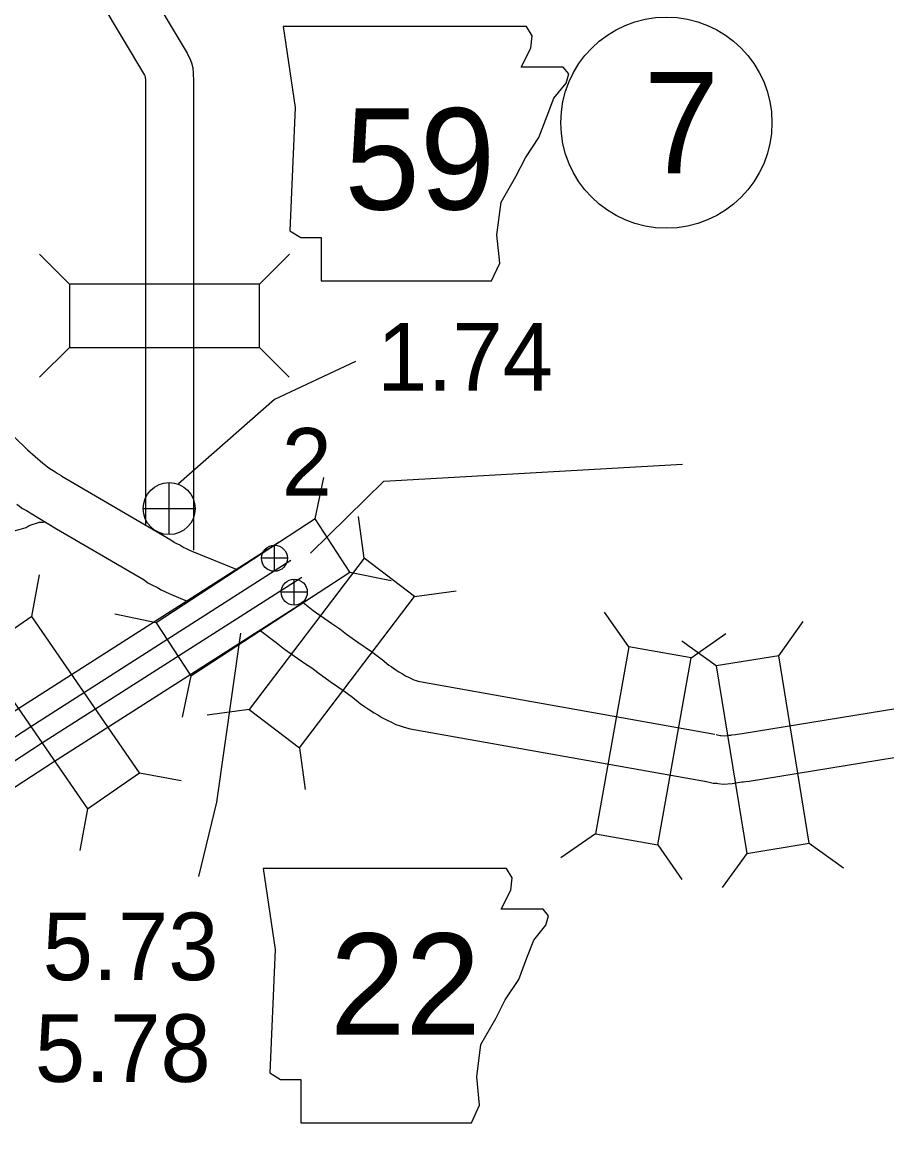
# Model space of a CAD drawing. Extents: x -939622 to -934245, y 1383184 to 1385301.
# Drawn here: x -936388.54 to -936372.33, y 1384539.92 to 1384560.75 of the extents above; entities that cross this region are included whole.
import ezdxf

# ---------------------------------------------------------------- set-up
doc = ezdxf.new("R2010")
doc.units = 0
for name, color, linetype in [('Level 10', 7, 'Continuous'), ('Level 20', 7, 'Continuous'), ('Level 21', 7, 'Continuous'), ('Level 25', 7, 'Continuous'), ('Level 26', 7, 'Continuous'), ('Level 27', 7, 'Continuous')]:
    doc.layers.add(name, color=color, linetype=linetype)

msp = doc.modelspace()

# ---------------------------------------------------------------- linework, layer by layer
at = {"layer": 'Level 10'}
for points in [[(-936387.073, 1384562.893), (-936385.448, 1384560.175), (-936385.424, 1384560.119), (-936385.4, 1384560.072), (-936385.37, 1384559.993), (-936385.345, 1384559.897), (-936385.337, 1384559.8), (-936385.337, 1384559.765), (-936385.333, 1384559.682), (-936385.334, 1384550.854)], [(-936387.907, 1384562.535), (-936386.249, 1384559.761), (-936386.237, 1384559.733), (-936386.236, 1384559.731), (-936386.233, 1384559.661), (-936386.234, 1384551.336)], [(-936389.27, 1384553.543), (-936389.22, 1384553.489), (-936389.206, 1384553.47), (-936388.444, 1384552.735), (-936388.158, 1384552.482), (-936388.107, 1384552.445), (-936388.066, 1384552.408), (-936387.996, 1384552.365), (-936387.933, 1384552.327), (-936387.901, 1384552.304), (-936387.816, 1384552.254), (-936387.803, 1384552.24), (-936385.757, 1384551.045), (-936385.696, 1384550.999), (-936385.686, 1384550.994), (-936385.661, 1384550.982), (-936385.587, 1384550.949), (-936385.513, 1384550.905), (-936385.51, 1384550.903), (-936385.481, 1384550.891), (-936385.443, 1384550.87), (-936385.405, 1384550.853), (-936385.365, 1384550.834), (-936384.533, 1384550.494)], [(-936388.642, 1384551.715), (-936388.537, 1384551.631), (-936388.476, 1384551.604), (-936388.463, 1384551.596), (-936388.429, 1384551.576), (-936388.394, 1384551.551), (-936387.898, 1384551.254), (-936386.257, 1384550.295), (-936386.185, 1384550.241), (-936386.086, 1384550.187), (-936386.033, 1384550.163), (-936386.004, 1384550.15), (-936385.988, 1384550.14), (-936385.936, 1384550.107), (-936385.87, 1384550.078), (-936385.841, 1384550.063), (-936385.789, 1384550.039), (-936385.733, 1384550.012), (-936385.461, 1384549.901)], [(-936389.709, 1384551.062), (-936389.691, 1384551.062), (-936389.682, 1384551.062), (-936389.665, 1384551.061), (-936389.547, 1384551.054), (-936389.523, 1384551.056), (-936389.449, 1384551.046), (-936389.302, 1384551.066), (-936389.211, 1384551.095), (-936389.211, 1384551.095), (-936389.167, 1384551.102), (-936388.694, 1384551.216), (-936388.599, 1384551.238), (-936388.47, 1384551.278), (-936388.411, 1384551.315), (-936388.221, 1384551.376), (-936388.219, 1384551.377), (-936388.209, 1384551.378), (-936388.153, 1384551.378), (-936388.109, 1384551.387)], [(-936412.105, 1384514.693), (-936411.981, 1384515.99), (-936411.897, 1384516.546), (-936411.613, 1384517.695), (-936411.366, 1384518.854), (-936411.114, 1384519.957), (-936410.855, 1384520.897), (-936410.434, 1384521.998), (-936409.873, 1384523.209), (-936409.418, 1384524.021), (-936408.853, 1384524.894), (-936407.084, 1384527.227), (-936404.629, 1384530.336), (-936402.743, 1384532.684), (-936399.705, 1384536.545), (-936395.754, 1384541.531), (-936393.808, 1384543.949), (-936392.835, 1384544.906), (-936391.967, 1384545.627), (-936390.884, 1384546.408), (-936388.606, 1384547.89), (-936383.726, 1384551.009)], [(-936411.715, 1384514.439), (-936411.571, 1384515.94), (-936411.492, 1384516.465), (-936411.211, 1384517.603), (-936410.963, 1384518.765), (-936410.714, 1384519.856), (-936410.462, 1384520.768), (-936410.054, 1384521.837), (-936409.505, 1384523.021), (-936409.065, 1384523.808), (-936408.515, 1384524.656), (-936406.758, 1384526.975), (-936404.306, 1384530.079), (-936402.42, 1384532.427), (-936399.382, 1384536.289), (-936395.432, 1384541.274), (-936393.502, 1384543.672), (-936392.558, 1384544.6), (-936391.714, 1384545.301), (-936390.651, 1384546.067), (-936388.383, 1384547.544), (-936383.504, 1384550.662)], [(-936411.365, 1384514.165), (-936411.199, 1384515.894), (-936411.123, 1384516.392), (-936410.846, 1384517.519), (-936410.597, 1384518.684), (-936410.35, 1384519.764), (-936410.106, 1384520.651), (-936409.708, 1384521.691), (-936409.171, 1384522.85), (-936408.743, 1384523.614), (-936408.208, 1384524.441), (-936406.461, 1384526.745), (-936404.013, 1384529.845), (-936402.127, 1384532.194), (-936399.087, 1384536.057), (-936395.139, 1384541.04), (-936393.223, 1384543.419), (-936392.306, 1384544.321), (-936391.484, 1384545.004), (-936390.439, 1384545.758), (-936388.179, 1384547.229), (-936383.302, 1384550.346)], [(-936410.98, 1384513.863), (-936410.789, 1384515.843), (-936410.718, 1384516.312), (-936410.444, 1384517.426), (-936410.194, 1384518.595), (-936409.95, 1384519.663), (-936409.713, 1384520.522), (-936409.328, 1384521.531), (-936408.804, 1384522.662), (-936408.39, 1384523.401), (-936407.87, 1384524.204), (-936406.135, 1384526.493), (-936403.69, 1384529.588), (-936401.804, 1384531.937), (-936398.764, 1384535.801), (-936394.816, 1384540.782), (-936392.917, 1384543.142), (-936392.029, 1384544.015), (-936391.232, 1384544.678), (-936390.206, 1384545.417), (-936387.956, 1384546.882), (-936383.08, 1384549.998)], [(-936383.278, 1384549.872), (-936383.086, 1384549.718), (-936382.739, 1384549.475), (-936382.59, 1384549.376), (-936382.463, 1384549.278), (-936382.252, 1384549.126), (-936381.994, 1384548.95), (-936381.791, 1384548.8), (-936381.671, 1384548.698), (-936381.626, 1384548.669), (-936381.539, 1384548.61), (-936381.478, 1384548.571), (-936381.412, 1384548.533), (-936381.354, 1384548.497), (-936381.3, 1384548.469), (-936381.252, 1384548.447), (-936381.199, 1384548.421), (-936381.159, 1384548.408), (-936381.121, 1384548.394), (-936381.085, 1384548.386), (-936375.553, 1384547.4)], [(-936384.088, 1384549.354), (-936383.78, 1384549.122), (-936383.626, 1384548.998), (-936383.248, 1384548.732), (-936383.113, 1384548.642), (-936382.999, 1384548.556), (-936382.769, 1384548.389), (-936382.514, 1384548.216), (-936382.349, 1384548.093), (-936382.209, 1384547.975), (-936382.127, 1384547.921), (-936382.033, 1384547.857), (-936381.943, 1384547.8), (-936381.876, 1384547.762), (-936381.802, 1384547.716), (-936381.699, 1384547.661), (-936381.632, 1384547.631), (-936381.535, 1384547.585), (-936381.455, 1384547.558), (-936381.378, 1384547.531), (-936381.269, 1384547.504), (-936375.711, 1384546.514)], [(-936375.53, 1384547.395), (-936375.454, 1384547.378), (-936375.443, 1384547.377), (-936375.367, 1384547.369), (-936375.366, 1384547.368), (-936375.292, 1384547.383), (-936375.258, 1384547.381), (-936375.238, 1384547.386), (-936375.169, 1384547.396), (-936375.134, 1384547.4), (-936375.087, 1384547.406), (-936375.044, 1384547.412), (-936370.818, 1384548.101), (-936366.161, 1384549.005), (-936365.952, 1384549.054), (-936365.245, 1384549.263)], [(-936375.734, 1384546.519), (-936375.587, 1384546.484), (-936375.521, 1384546.48), (-936375.494, 1384546.477), (-936375.402, 1384546.461), (-936375.233, 1384546.476), (-936375.051, 1384546.504), (-936375.027, 1384546.507), (-936374.972, 1384546.514), (-936374.914, 1384546.521), (-936370.66, 1384547.215), (-936365.974, 1384548.125), (-936365.722, 1384548.183), (-936365.504, 1384548.248)]]:
    msp.add_lwpolyline(points, dxfattribs=at)
at = {"layer": 'Level 20'}
for p, q in [((-936387.658, 1384555.844), (-936388.218, 1384556.404)), ((-936384.094, 1384555.844), (-936383.534, 1384556.403)), ((-936387.659, 1384554.656), (-936388.219, 1384554.096)), ((-936384.095, 1384554.656), (-936383.535, 1384554.095)), ((-936383.05, 1384551.437), (-936382.887, 1384552.212)), ((-936382.133, 1384550.701), (-936382.24, 1384551.486)), ((-936388.364, 1384549.608), (-936388.22, 1384550.387)), ((-936382.4, 1384550.442), (-936381.625, 1384550.28)), ((-936381.187, 1384549.982), (-936380.403, 1384550.089)), ((-936377.17, 1384549.041), (-936377.624, 1384549.691)), ((-936386.034, 1384549.488), (-936386.809, 1384549.65)), ((-936374.358, 1384548.873), (-936373.896, 1384549.516)), ((-936376.001, 1384548.833), (-936375.351, 1384549.286)), ((-936375.531, 1384548.682), (-936376.173, 1384549.145)), ((-936385.384, 1384548.493), (-936385.546, 1384547.718)), ((-936384.29, 1384547.864), (-936385.075, 1384547.757)), ((-936383.344, 1384547.145), (-936383.237, 1384546.36)), ((-936386.344, 1384546.673), (-936385.565, 1384546.529)), ((-936387.322, 1384545.999), (-936387.466, 1384545.22)), ((-936377.796, 1384545.532), (-936378.445, 1384545.079)), ((-936376.626, 1384545.324), (-936376.173, 1384544.674)), ((-936373.784, 1384545.356), (-936373.141, 1384544.893)), ((-936374.957, 1384545.165), (-936375.419, 1384544.522))]:
    msp.add_line(p, q, dxfattribs=at)
for points in [[(-936384.094, 1384555.844), (-936387.658, 1384555.844), (-936387.659, 1384554.656), (-936384.095, 1384554.656)], [(-936383.05, 1384551.437), (-936386.034, 1384549.488), (-936385.384, 1384548.493), (-936382.4, 1384550.442)], [(-936382.133, 1384550.701), (-936384.29, 1384547.864), (-936383.344, 1384547.145), (-936381.187, 1384549.982)], [(-936386.344, 1384546.673), (-936388.364, 1384549.608), (-936389.343, 1384548.935), (-936387.322, 1384545.999)], [(-936377.17, 1384549.041), (-936377.796, 1384545.532), (-936376.626, 1384545.324), (-936376.001, 1384548.833)], [(-936373.784, 1384545.356), (-936374.358, 1384548.873), (-936375.531, 1384548.682), (-936374.957, 1384545.165)]]:
    msp.add_lwpolyline(points, close=True, dxfattribs=at)
at = {"layer": 'Level 21'}
for points in [[(-936383.65, 1384560.675), (-936383.422, 1384559.152), (-936383.523, 1384556.843), (-936383.32, 1384556.716), (-936382.94, 1384556.716), (-936382.94, 1384555.904), (-936379.742, 1384555.904), (-936379.59, 1384556.234), (-936379.641, 1384556.767), (-936379.565, 1384557.376), (-936379.285, 1384557.858), (-936379.108, 1384558.213), (-936378.854, 1384558.594), (-936378.702, 1384559), (-936378.575, 1384559.33), (-936378.346, 1384559.609), (-936378.296, 1384559.787), (-936378.397, 1384559.914), (-936379.184, 1384559.914), (-936379.006, 1384560.269), (-936378.981, 1384560.497), (-936379.086, 1384560.673)], [(-936384.027, 1384544.882), (-936383.799, 1384543.36), (-936383.9, 1384541.05), (-936383.697, 1384540.923), (-936383.317, 1384540.923), (-936383.317, 1384540.111), (-936380.119, 1384540.111), (-936379.967, 1384540.441), (-936380.018, 1384540.974), (-936379.942, 1384541.583), (-936379.662, 1384542.065), (-936379.485, 1384542.421), (-936379.231, 1384542.801), (-936379.079, 1384543.207), (-936378.952, 1384543.537), (-936378.723, 1384543.816), (-936378.673, 1384543.994), (-936378.774, 1384544.121), (-936379.561, 1384544.121), (-936379.383, 1384544.476), (-936379.358, 1384544.705), (-936379.463, 1384544.88)]]:
    msp.add_lwpolyline(points, close=True, dxfattribs=at)
msp.add_lwpolyline([(-936383.14, 1384550.793), (-936381.762, 1384552.148), (-936376.159, 1384552.464)], dxfattribs=at)
at = {"layer": 'Level 25'}
for points in [[(-936382.293, 1384554.393), (-936383.812, 1384553.679), (-936385.611, 1384552.097)], [(-936384.449, 1384549.296), (-936384.898, 1384546.125), (-936385.239, 1384544.729)]]:
    msp.add_lwpolyline(points, dxfattribs=at)
at = {"layer": 'Level 26'}
for p, q in [((-936385.788, 1384551.145), (-936385.788, 1384552.12)), ((-936386.275, 1384551.632), (-936385.3, 1384551.632)), ((-936383.814, 1384550.456), (-936383.814, 1384550.944)), ((-936383.57, 1384550.7), (-936384.058, 1384550.7)), ((-936383.442, 1384549.82), (-936383.442, 1384550.308)), ((-936383.198, 1384550.064), (-936383.686, 1384550.064))]:
    msp.add_line(p, q, dxfattribs=at)
for centre, radius in [((-936385.788, 1384551.632), 0.487), ((-936383.814, 1384550.7), 0.244), ((-936383.442, 1384550.064), 0.244)]:
    msp.add_circle(centre, radius, dxfattribs=at)
at = {"layer": 'Level 27'}
msp.add_ellipse((-936376.464, 1384558.87), major_axis=(0, 1.98), ratio=0.999998, dxfattribs=at)

# ---------------------------------------------------------------- texts
at = {"layer": 'Level 20'}
msp.add_text('2', height=1.267, dxfattribs=at).set_placement((-936383.677, 1384551.875))
at = {"layer": 'Level 21'}
for s, p in [('59', (-936382.5, 1384557.241)), ('22', (-936382.773, 1384541.764))]:
    msp.add_text(s, height=1.9008, dxfattribs=at).set_placement(p)
at = {"layer": 'Level 25'}
for s, p in [('1.74', (-936381.888, 1384553.845)), ('5.73', (-936388.16, 1384542.787)), ('5.78', (-936388.307, 1384540.879))]:
    msp.add_text(s, height=1.2672, dxfattribs=at).set_placement(p)
at = {"layer": 'Level 27'}
msp.add_text('7', height=1.901, dxfattribs=at).set_placement((-936376.889, 1384557.919))

doc.saveas('drawing.dxf')
